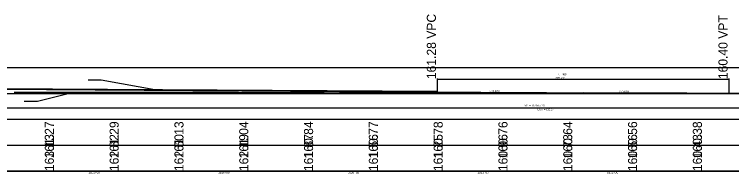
# Model space of a CAD drawing. Extents: x 2126510 to 2136144, y 865066 to 868066.
# Drawn here: x 2134341 to 2134895, y 867812 to 867936 of the extents above; entities that cross this region are included whole.
import ezdxf

# ---------------------------------------------------------------- set-up
doc = ezdxf.new("R2010")
doc.units = 0
for name, color, linetype in [('RD_EX_GuardRail', 7, 'Continuous'), ('RD_EX_H2O', 7, 'Continuous'), ('RD_EX_Misc', 7, 'Continuous'), ('RD_EX_UT', 7, 'Continuous')]:
    doc.layers.add(name, color=color, linetype=linetype)

msp = doc.modelspace()

# ---------------------------------------------------------------- linework, layer by layer
at = {"layer": 'RD_EX_GuardRail'}
for p, q in [((2135251.98, 867894.32), (2130671.73, 867894.32)), ((2135251.98, 867874.32), (2133154.4, 867874.32)), ((2135251.98, 867854.32), (2130671.73, 867854.32)), ((2135251.98, 867834.32), (2130671.73, 867834.32)), ((2135251.98, 867814.32), (2130671.73, 867814.32))]:
    msp.add_line(p, q, dxfattribs=at)
at = {"layer": 'RD_EX_H2O'}
for points in [[(2134341.47, 867875.6), (2134342.47, 867875.6), (2134343.47, 867875.6), (2134344.47, 867875.6), (2134345.47, 867875.6), (2134346.47, 867875.59), (2134347.47, 867875.59), (2134348.47, 867875.59), (2134349.47, 867875.58), (2134350.47, 867875.58), (2134351.47, 867875.58), (2134352.47, 867875.58), (2134353.47, 867875.58), (2134354.47, 867875.58), (2134355.47, 867875.57), (2134356.47, 867875.57), (2134357.47, 867875.57), (2134358.47, 867875.57), (2134359.47, 867875.57), (2134360.47, 867875.57), (2134361.47, 867875.57), (2134362.47, 867875.58), (2134363.47, 867875.58), (2134364.47, 867875.58), (2134365.47, 867875.58), (2134366.47, 867875.58), (2134367.47, 867875.58), (2134368.47, 867875.58), (2134369.47, 867875.58), (2134370.47, 867875.58), (2134371.47, 867875.58), (2134372.47, 867875.58), (2134373.47, 867875.58), (2134374.47, 867875.58), (2134375.47, 867875.58), (2134376.47, 867875.58), (2134377.47, 867875.59), (2134378.47, 867875.59), (2134379.47, 867875.59), (2134380.47, 867875.59), (2134381.47, 867875.59), (2134382.47, 867875.59), (2134383.47, 867875.59), (2134384.47, 867875.59), (2134385.47, 867875.59), (2134386.47, 867875.59)], [(2134386.47, 867875.59), (2134387.47, 867875.59), (2134388.47, 867875.6), (2134389.47, 867875.6), (2134390.47, 867875.6), (2134391.47, 867875.6), (2134392.47, 867875.6), (2134393.47, 867875.6), (2134394.47, 867875.61), (2134395.47, 867875.61), (2134396.47, 867875.61), (2134397.47, 867875.61), (2134398.47, 867875.61), (2134399.47, 867875.61), (2134400.47, 867875.61), (2134401.47, 867875.62), (2134402.47, 867875.62), (2134403.47, 867875.62), (2134404.47, 867875.62), (2134405.47, 867875.62), (2134406.47, 867875.62), (2134407.47, 867875.63), (2134408.47, 867875.63), (2134409.47, 867875.62), (2134410.47, 867875.62), (2134411.47, 867875.62), (2134412.47, 867875.62), (2134413.47, 867875.62), (2134414.47, 867875.62), (2134415.47, 867875.62), (2134416.47, 867875.62), (2134417.47, 867875.61), (2134418.47, 867875.61), (2134419.47, 867875.61), (2134420.47, 867875.61), (2134421.47, 867875.61), (2134422.47, 867875.61), (2134423.47, 867875.61), (2134424.47, 867875.61), (2134425.47, 867875.6), (2134426.47, 867875.6), (2134427.47, 867875.6), (2134428.47, 867875.6), (2134429.47, 867875.6), (2134430.47, 867875.6), (2134431.47, 867875.59), (2134432.47, 867875.59), (2134433.47, 867875.59), (2134434.47, 867875.59), (2134435.47, 867875.59), (2134436.47, 867875.59), (2134437.47, 867875.59), (2134438.47, 867875.58), (2134439.47, 867875.58), (2134440.47, 867875.58), (2134441.47, 867875.58), (2134442.47, 867875.58), (2134443.47, 867875.58), (2134444.47, 867875.57), (2134445.47, 867875.57), (2134446.47, 867875.57), (2134447.47, 867875.57), (2134448.47, 867875.57), (2134449.47, 867875.57), (2134450.47, 867875.56), (2134451.47, 867875.56), (2134452.47, 867875.56), (2134453.47, 867875.56), (2134454.47, 867875.56), (2134455.47, 867875.55), (2134456.47, 867875.54), (2134457.47, 867875.54), (2134458.47, 867875.53), (2134459.47, 867875.52), (2134460.47, 867875.52), (2134461.47, 867875.51), (2134462.47, 867875.5), (2134463.47, 867875.5), (2134464.47, 867875.49), (2134465.47, 867875.48), (2134466.47, 867875.48), (2134467.47, 867875.47), (2134468.47, 867875.47), (2134469.47, 867875.46), (2134470.47, 867875.45), (2134471.47, 867875.45), (2134472.47, 867875.45), (2134473.47, 867875.45), (2134474.47, 867875.45), (2134475.47, 867875.45), (2134476.47, 867875.44), (2134477.47, 867875.44), (2134478.47, 867875.44), (2134479.47, 867875.44), (2134480.47, 867875.44), (2134481.47, 867875.44), (2134482.47, 867875.44), (2134483.47, 867875.44), (2134484.47, 867875.43), (2134485.47, 867875.43), (2134486.47, 867875.43)], [(2134486.47, 867875.43), (2134487.47, 867875.43), (2134488.47, 867875.43), (2134489.47, 867875.43), (2134490.47, 867875.43), (2134491.47, 867875.43), (2134492.47, 867875.43), (2134493.47, 867875.43), (2134494.47, 867875.43), (2134495.47, 867875.43), (2134496.47, 867875.43), (2134497.47, 867875.43), (2134498.47, 867875.43), (2134499.47, 867875.43), (2134500.47, 867875.43), (2134501.47, 867875.43), (2134502.47, 867875.43), (2134503.47, 867875.42), (2134504.47, 867875.42), (2134505.47, 867875.42), (2134506.47, 867875.42), (2134507.47, 867875.42), (2134508.47, 867875.42), (2134509.47, 867875.42), (2134510.47, 867875.41), (2134511.47, 867875.41), (2134512.47, 867875.41), (2134513.47, 867875.4), (2134514.47, 867875.4), (2134515.47, 867875.39), (2134516.47, 867875.39), (2134517.47, 867875.38), (2134518.47, 867875.38), (2134519.47, 867875.37), (2134520.47, 867875.37), (2134521.47, 867875.36), (2134522.47, 867875.36), (2134523.47, 867875.35), (2134524.47, 867875.35), (2134525.47, 867875.34), (2134526.47, 867875.34), (2134527.47, 867875.33), (2134528.47, 867875.33), (2134529.47, 867875.32), (2134530.47, 867875.32), (2134531.47, 867875.31), (2134532.47, 867875.31), (2134533.47, 867875.3), (2134534.47, 867875.3), (2134535.47, 867875.29), (2134536.47, 867875.29), (2134537.47, 867875.28), (2134538.47, 867875.28), (2134539.47, 867875.27), (2134540.47, 867875.26), (2134541.47, 867875.26), (2134542.47, 867875.25), (2134543.47, 867875.25), (2134544.47, 867875.24), (2134545.47, 867875.24), (2134546.47, 867875.23), (2134547.47, 867875.23), (2134548.47, 867875.22), (2134549.47, 867875.22), (2134550.47, 867875.22), (2134551.47, 867875.21), (2134552.47, 867875.21), (2134553.47, 867875.21), (2134554.47, 867875.21), (2134555.47, 867875.2), (2134556.47, 867875.2), (2134557.47, 867875.2), (2134558.47, 867875.2), (2134559.47, 867875.2), (2134560.47, 867875.19), (2134561.47, 867875.19), (2134562.47, 867875.19), (2134563.47, 867875.19), (2134564.47, 867875.18), (2134565.47, 867875.18), (2134566.47, 867875.18), (2134567.47, 867875.18), (2134568.47, 867875.17), (2134569.47, 867875.17), (2134570.47, 867875.17), (2134571.47, 867875.17), (2134572.47, 867875.16), (2134573.47, 867875.16), (2134574.47, 867875.16), (2134575.47, 867875.15), (2134576.47, 867875.15), (2134577.47, 867875.15), (2134578.47, 867875.14), (2134579.47, 867875.14), (2134580.47, 867875.14), (2134581.47, 867875.13), (2134582.47, 867875.13), (2134583.47, 867875.13), (2134584.47, 867875.12), (2134585.47, 867875.12), (2134586.47, 867875.12)], [(2134586.47, 867875.12), (2134587.47, 867875.12), (2134588.47, 867875.11), (2134589.47, 867875.11), (2134590.47, 867875.11), (2134591.47, 867875.11), (2134592.47, 867875.11), (2134593.47, 867875.11), (2134594.47, 867875.11), (2134595.47, 867875.11), (2134596.47, 867875.11), (2134597.47, 867875.11), (2134598.47, 867875.11), (2134599.47, 867875.1), (2134600.47, 867875.1), (2134601.47, 867875.1), (2134602.47, 867875.1), (2134603.47, 867875.1), (2134604.47, 867875.1), (2134605.47, 867875.1), (2134606.47, 867875.1), (2134607.47, 867875.1), (2134608.47, 867875.1), (2134609.47, 867875.1), (2134610.47, 867875.09), (2134611.47, 867875.09), (2134612.47, 867875.09), (2134613.47, 867875.09), (2134614.47, 867875.09), (2134615.47, 867875.09), (2134616.47, 867875.09), (2134617.47, 867875.09), (2134618.47, 867875.09), (2134619.47, 867875.09), (2134620.47, 867875.08), (2134621.47, 867875.08), (2134622.47, 867875.08), (2134623.47, 867875.08), (2134624.47, 867875.08), (2134625.47, 867875.08), (2134626.47, 867875.08), (2134627.47, 867875.08), (2134628.47, 867875.08), (2134629.47, 867875.08), (2134630.47, 867875.08), (2134631.47, 867875.08), (2134632.47, 867875.08), (2134633.47, 867875.08), (2134634.47, 867875.09), (2134635.47, 867875.09), (2134636.47, 867875.09), (2134637.47, 867875.09), (2134638.47, 867875.09), (2134639.47, 867875.09), (2134640.47, 867875.09), (2134641.47, 867875.09), (2134642.47, 867875.09), (2134643.47, 867875.09), (2134644.47, 867875.09), (2134645.47, 867875.09), (2134646.47, 867875.09), (2134647.47, 867875.09), (2134648.47, 867875.09), (2134649.47, 867875.09), (2134650.47, 867875.09), (2134651.47, 867875.09), (2134652.47, 867875.09), (2134653.47, 867875.09), (2134654.47, 867875.09), (2134655.47, 867875.09), (2134656.47, 867875.09), (2134657.47, 867875.09), (2134658.47, 867875.09), (2134659.47, 867875.09), (2134660.47, 867875.09), (2134661.47, 867875.09), (2134662.47, 867875.09), (2134663.47, 867875.09), (2134664.47, 867875.09), (2134665.47, 867875.09), (2134666.47, 867875.1), (2134667.47, 867875.1), (2134668.47, 867875.1), (2134669.47, 867875.1), (2134670.47, 867875.1), (2134671.47, 867875.1), (2134672.47, 867875.1), (2134673.47, 867875.1), (2134674.47, 867875.1), (2134675.47, 867875.1), (2134676.47, 867875.1), (2134677.47, 867875.1), (2134678.47, 867875.1), (2134679.47, 867875.1), (2134680.47, 867875.1), (2134681.47, 867875.1), (2134682.47, 867875.1), (2134683.47, 867875.1), (2134684.47, 867875.1), (2134685.47, 867875.1), (2134686.47, 867875.1)], [(2134686.47, 867875.1), (2134687.47, 867875.11), (2134688.47, 867875.11), (2134689.47, 867875.11), (2134690.47, 867875.11), (2134691.47, 867875.11), (2134692.47, 867875.11), (2134693.47, 867875.11), (2134694.47, 867875.11), (2134695.47, 867875.11), (2134696.47, 867875.11), (2134697.47, 867875.11), (2134698.47, 867875.11), (2134699.47, 867875.11), (2134700.47, 867875.11), (2134701.47, 867875.11), (2134702.47, 867875.11), (2134703.47, 867875.11), (2134704.47, 867875.11), (2134705.47, 867875.11), (2134706.47, 867875.11), (2134707.47, 867875.1), (2134708.47, 867875.1), (2134709.47, 867875.1), (2134710.47, 867875.1), (2134711.47, 867875.1), (2134712.47, 867875.09), (2134713.47, 867875.09), (2134714.47, 867875.09), (2134715.47, 867875.09), (2134716.47, 867875.09), (2134717.47, 867875.09), (2134718.47, 867875.08), (2134719.47, 867875.08), (2134720.47, 867875.08), (2134721.47, 867875.08), (2134722.47, 867875.08), (2134723.47, 867875.07), (2134724.47, 867875.07), (2134725.47, 867875.07), (2134726.47, 867875.07), (2134727.47, 867875.07), (2134728.47, 867875.06), (2134729.47, 867875.06), (2134730.47, 867875.05), (2134731.47, 867875.05), (2134732.47, 867875.05), (2134733.47, 867875.04), (2134734.47, 867875.04), (2134735.47, 867875.03), (2134736.47, 867875.03), (2134737.47, 867875.03), (2134738.47, 867875.02), (2134739.47, 867875.02), (2134740.47, 867875.01), (2134741.47, 867875.01), (2134742.47, 867875), (2134743.47, 867875), (2134744.47, 867875), (2134745.47, 867875), (2134746.47, 867874.99), (2134747.47, 867874.99), (2134748.47, 867874.99), (2134749.47, 867874.99), (2134750.47, 867874.99), (2134751.47, 867874.99), (2134752.47, 867874.99), (2134753.47, 867874.98), (2134754.47, 867874.98), (2134755.47, 867874.98), (2134756.47, 867874.98), (2134757.47, 867874.98), (2134758.47, 867874.98), (2134759.47, 867874.97), (2134760.47, 867874.97), (2134761.47, 867874.97), (2134762.47, 867874.97), (2134763.47, 867874.97), (2134764.47, 867874.97), (2134765.47, 867874.97), (2134766.47, 867874.96), (2134767.47, 867874.96), (2134768.47, 867874.96), (2134769.47, 867874.96), (2134770.47, 867874.96), (2134771.47, 867874.96), (2134772.47, 867874.95), (2134773.47, 867874.95), (2134774.47, 867874.95), (2134775.47, 867874.95), (2134776.47, 867874.95), (2134777.47, 867874.95), (2134778.47, 867874.95), (2134779.47, 867874.94), (2134780.47, 867874.94), (2134781.47, 867874.94), (2134782.47, 867874.94), (2134783.47, 867874.94), (2134784.47, 867874.93), (2134785.47, 867874.93), (2134786.47, 867874.93)]]:
    msp.add_lwpolyline(points, dxfattribs=at)
at = {"layer": 'RD_EX_Misc'}
for p, q in [((2133649.16, 867882.7), (2134667.76, 867876.29)), ((2134667.76, 867886.09), (2134667.76, 867875.59)), ((2134667.76, 867885.59), (2134892.76, 867885.59)), ((2134892.76, 867886.09), (2134892.76, 867874.72)), ((2134700.3, 867875.39), (2134780.26, 867874.88)), ((2134860.25, 867874.76), (2134780.26, 867874.88)), ((2134892.76, 867874.72), (2134904.26, 867874.7)), ((2131523, 867814.32), (2135677.25, 867814.32))]:
    msp.add_line(p, q, dxfattribs=at)
for points in [[(2134398.45, 867885.15), (2134408.38, 867885.15), (2134452.66, 867876.95)], [(2134349.16, 867868.52), (2134359.36, 867868.52), (2134387.13, 867875.59)], [(2134786.47, 867874.93), (2134787.47, 867874.93), (2134788.47, 867874.93), (2134789.47, 867874.92), (2134790.47, 867874.92), (2134791.47, 867874.92), (2134792.47, 867874.92), (2134793.47, 867874.91), (2134794.47, 867874.91), (2134795.47, 867874.91), (2134796.47, 867874.91), (2134797.47, 867874.9), (2134798.47, 867874.9), (2134799.47, 867874.9), (2134800.47, 867874.9), (2134801.47, 867874.9), (2134802.47, 867874.89), (2134803.47, 867874.89), (2134804.47, 867874.89), (2134805.47, 867874.89), (2134806.47, 867874.88), (2134807.47, 867874.88), (2134808.47, 867874.88), (2134809.47, 867874.88), (2134810.47, 867874.88), (2134811.47, 867874.88), (2134812.47, 867874.88), (2134813.47, 867874.88), (2134814.47, 867874.88), (2134815.47, 867874.88), (2134816.47, 867874.88), (2134817.47, 867874.88), (2134818.47, 867874.88), (2134819.47, 867874.87), (2134820.47, 867874.87), (2134821.47, 867874.87), (2134822.47, 867874.87), (2134823.47, 867874.87), (2134824.47, 867874.87), (2134825.47, 867874.87), (2134826.47, 867874.86), (2134827.47, 867874.86), (2134828.47, 867874.85), (2134829.47, 867874.85), (2134830.47, 867874.84), (2134831.47, 867874.84), (2134832.47, 867874.84), (2134833.47, 867874.83), (2134834.47, 867874.83), (2134835.47, 867874.82), (2134836.47, 867874.82), (2134837.47, 867874.81), (2134838.47, 867874.81), (2134839.47, 867874.8), (2134840.47, 867874.8), (2134841.47, 867874.79), (2134842.47, 867874.79), (2134843.47, 867874.78), (2134844.47, 867874.78), (2134845.47, 867874.77), (2134846.47, 867874.77), (2134847.47, 867874.76), (2134848.47, 867874.76), (2134849.47, 867874.75), (2134850.47, 867874.75), (2134851.47, 867874.74), (2134852.47, 867874.74), (2134853.47, 867874.74), (2134854.47, 867874.73), (2134855.47, 867874.73), (2134856.47, 867874.72), (2134857.47, 867874.72), (2134858.47, 867874.71), (2134859.47, 867874.71), (2134860.47, 867874.7), (2134861.47, 867874.7), (2134862.47, 867874.69), (2134863.47, 867874.69), (2134864.47, 867874.69), (2134865.47, 867874.68), (2134866.47, 867874.69), (2134867.47, 867874.69), (2134868.47, 867874.69), (2134869.47, 867874.69), (2134870.47, 867874.69), (2134871.47, 867874.69), (2134872.47, 867874.69), (2134873.47, 867874.69), (2134874.47, 867874.7), (2134875.47, 867874.7), (2134876.47, 867874.7), (2134877.47, 867874.7), (2134878.47, 867874.7), (2134879.47, 867874.7), (2134880.47, 867874.7), (2134881.47, 867874.7), (2134882.47, 867874.71), (2134883.47, 867874.71), (2134884.47, 867874.71), (2134885.47, 867874.71), (2134886.47, 867874.71)], [(2134886.47, 867874.71), (2134887.47, 867874.71), (2134888.47, 867874.71), (2134889.47, 867874.71), (2134890.47, 867874.71), (2134891.47, 867874.71), (2134892.47, 867874.71), (2134893.47, 867874.71), (2134894.47, 867874.71), (2134895.47, 867874.71)], [(2131430.13, 867814.32), (2131430.13, 867863.32), (2136143.96, 867863.32)]]:
    msp.add_lwpolyline(points, dxfattribs=at)
msp.add_spline([(2134667.76, 867875.59), (2134672.26, 867875.56), (2134676.76, 867875.54), (2134681.26, 867875.51), (2134685.76, 867875.48), (2134690.26, 867875.46), (2134694.76, 867875.43), (2134699.26, 867875.41), (2134703.76, 867875.38), (2134708.26, 867875.36), (2134712.76, 867875.33), (2134717.26, 867875.31), (2134721.76, 867875.28), (2134726.26, 867875.26), (2134730.76, 867875.24), (2134735.26, 867875.22), (2134739.76, 867875.19), (2134744.26, 867875.17), (2134748.76, 867875.15), (2134753.26, 867875.13), (2134757.76, 867875.11), (2134762.26, 867875.09), (2134766.76, 867875.07), (2134771.26, 867875.06), (2134775.76, 867875.04), (2134780.26, 867875.02), (2134784.76, 867875), (2134789.26, 867874.99), (2134793.76, 867874.97), (2134798.26, 867874.95), (2134802.76, 867874.94), (2134807.26, 867874.92), (2134811.76, 867874.91), (2134816.26, 867874.89), (2134820.76, 867874.88), (2134825.26, 867874.87), (2134829.76, 867874.85), (2134834.26, 867874.84), (2134838.76, 867874.83), (2134843.26, 867874.82), (2134847.76, 867874.8), (2134852.26, 867874.79), (2134856.76, 867874.78), (2134861.26, 867874.77), (2134865.76, 867874.76), (2134870.26, 867874.75), (2134874.76, 867874.75), (2134879.26, 867874.74), (2134883.76, 867874.73), (2134888.26, 867874.72), (2134892.76, 867874.72)], degree=3, dxfattribs=at)
at = {"layer": 'RD_EX_UT'}
msp.add_line((2133649.16, 867882.01), (2134667.76, 867875.59), dxfattribs=at)

# ---------------------------------------------------------------- texts
at = {"layer": 'RD_EX_Misc'}
for s, height, rotation, p in [('161.28 VPC', 7, 90, (2134666.76, 867885.59)), ('160.40 VPT', 7, 90, (2134891.76, 867885.59)), ('(-) 0.63%', 1.417, 359.6391, (2134708.04, 867875.74)), ('(-) 0.15%', 1.401, 359.9141, (2134807.95, 867875.24)), ('161.27', 7, 90, (2134372, 867824.32)), ('161.29', 7, 90, (2134422, 867824.32)), ('161.13', 7, 90, (2134472, 867824.32)), ('161.04', 7, 90, (2134522, 867824.32)), ('160.84', 7, 90, (2134572, 867824.32)), ('160.77', 7, 90, (2134622, 867824.32)), ('160.78', 7, 90, (2134672, 867824.32)), ('160.76', 7, 90, (2134722, 867824.32)), ('160.64', 7, 90, (2134772, 867824.32)), ('160.56', 7, 90, (2134822, 867824.32)), ('160.38', 7, 90, (2134872, 867824.32)), ('163.13', 7, 90, (2134372, 867814.47)), ('162.82', 7, 90, (2134422, 867814.47)), ('162.50', 7, 90, (2134472, 867814.47)), ('162.19', 7, 90, (2134522, 867814.47)), ('161.87', 7, 90, (2134572, 867814.47)), ('161.56', 7, 90, (2134622, 867814.47)), ('161.25', 7, 90, (2134672, 867814.47)), ('160.96', 7, 90, (2134722, 867814.47)), ('160.73', 7, 90, (2134772, 867814.47)), ('160.56', 7, 90, (2134822, 867814.47)), ('160.43', 7, 90, (2134872, 867814.47))]:
    msp.add_text(s, height=height, rotation=rotation, dxfattribs=at).set_placement(p)
for s, height, p in [('K = 469', 1.4, (2134760.7, 867888.64)), ("225' V.C.", 1.4, (2134759, 867885.84)), ('VPI = 1821+57.26', 1.4, (2134735.19, 867864.48)), ('Elev. = 160.57', 1.4, (2134745.2, 867861.48)), ('1818+00', 1.6, (2134398.79, 867812.52)), ('1819+00', 1.6, (2134498.79, 867812.52)), ('1820+00', 1.6, (2134598.79, 867812.52)), ('1821+00', 1.6, (2134698.79, 867812.52)), ('1822+00', 1.6, (2134798.79, 867812.52))]:
    msp.add_text(s, height=height, dxfattribs=at).set_placement(p)

doc.saveas('drawing.dxf')
